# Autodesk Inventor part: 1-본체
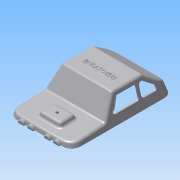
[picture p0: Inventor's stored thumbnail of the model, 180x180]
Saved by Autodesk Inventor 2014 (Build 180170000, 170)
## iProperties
Created: 2015-05
Part Number: 1-본체
Material: ABS 플라스틱
Document SubType Name: Modeling
Designer: Administrator
Density: 1.06 g/cm^3
Appearance: 매끄러움 - 흰색
Mass: 31.0436 g
Surface Area: 303.905 cm^2
Volume: 29.2864 cm^3
Author: Administrator
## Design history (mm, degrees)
sketch "스케치1"
  geometry: L1 (-61, 0)-(61, 0); L2 (61, 0)-(58.321, -10); L3 (-61, 0)-(-59.66, -5); L4 (-59.66, -5)-(-19, -7.131); L5 (-19, -7.131)-(-4.71, -30); L6 (-4.71, -30)-(31, -30); L7 (31, -30)-(58.321, -10); 2 further points
  constraints: 14 end point, 1 coincident, 1 horizontal, 1 midpoint, 1 parallel
  dimensions: "d28" = 122 distance of L1.start L1.end; "d29" = 105 deg angle of L1 L2; "d30" = 105 deg angle of L1 L3; "d31" = 3 deg angle of L1 L4; "d32" = 5 vertical distance of L1.start L3.end; "d33" = 125 deg angle of L5 L4; "d34" = 42 horizontal distance of L4.end L1.start; "d35" = 30 distance between parallel lines of L1 L6; "d36" = 30 horizontal distance of L1.end L6.end; "d37" = 20 vertical distance of L2.end L6.end
extrude "돌출1" new body sketch "스케치1" stored distance "d12" = 76; taper "d13" = 0 deg
node "작업 평면1"
sketch "스케치2"
  geometry: L1 (0, 38)-(0, -38) reference; L2 (-30, 38)-(-30, -38) reference; L3 (0, -38)-(-30, -29.962); L4 (0, 38)-(-30, 29.962); L5 (-30, -38)-(0, -38); L6 (-30, 38)-(0, 38); 3 further points
  constraints: 8 end point, 2 point on line, 1 parallel, 1 perpendicular
  dimensions: "d39" = 105 deg angle of L1 L3; "d40" = 105 deg angle of L1 L4
extrude "돌출2" cut sketch "스케치2" stored distance "d41" = 76; taper "d42" = 0 deg
sketch "스케치4"
  geometry: L1 (-59.66, -5)-(-19, -7.131) reference; L2 (-50.015, -5.505)-(-48.459, -10.594); L3 (-48.459, -10.594)-(-32.122, -11.45); L4 (-32.122, -11.45)-(-30.042, -6.552); 1 further point
  constraints: 6 end point, 2 point on line, 1 parallel
  dimensions: "d65" = 20 distance of L4.end L2.start
extrude "돌출4" join sketch "스케치4" stored distance "d68" = 26; taper "d69" = 0 deg
fillet "모깎기6" dims "d139" = 12
fillet "모깎기2" dims "d101" = 3
fillet "모깎기3" dims "d102" = 3
fillet "모깎기4" dims "d103" = 3
fillet "모깎기5" dims "d104" = 3
feature "쉘1" dims "d43" = 2
sketch "스케치3"
  geometry: L1 (-58.321, -10)-(-31, -30) reference; L2 (-31, -30)-(4.71, -30) reference; L3 (4.71, -30)-(19, -7.131) reference; L4 (2.819, -23.59)-(8.443, -14.59); L5 (5.899, -10)-(-19.689, -10); L6 (-22.689, -13)-(-22.689, -22); L7 (-19.689, -25)-(0.275, -25); L8 (-25.385, -22)-(-25.385, -13); L9 (-28.385, -10)-(-40.679, -10); L10 (-30.157, -24.421)-(-42.451, -15.421); A1 r 3 centre (5.899, -13) between (8.443, -14.59) and (5.899, -10); A2 r 3 centre (0.275, -22) between (0.275, -25) and (2.819, -23.59); A3 r 3 centre (-19.689, -13) between (-19.689, -10) and (-22.689, -13); A4 r 3 centre (-19.689, -22) between (-22.689, -22) and (-19.689, -25); A5 r 3 centre (-28.385, -22) between (-30.157, -24.421) and (-25.385, -22); A6 r 3 centre (-28.385, -13) between (-25.385, -13) and (-28.385, -10); A7 r 3 centre (-40.679, -13) between (-40.679, -10) and (-42.451, -15.421); 2 further points
  constraints: 14 end point, 14 point on circle, 14 tangent, 7 centre point, 4 perpendicular, 3 equal radius, 3 parallel, 2 point on line
  dimensions: "d45" = 5 distance between parallel lines of L3 L4; "d46" = 15 distance between parallel lines of L5 L7; "d47" = 34 distance from line of L6 point (11.311, -10); "d48" = 3 radius of A1; "d53" = 5 distance between parallel lines of L2 L7; "d54" = 3 radius of A5; "d55" = 5 distance edge to line of A5 L2; "d56" = 15 dimension on A5 L9; "d57" = 3 radius of A6; "d58" = 5 distance between parallel lines of L1 L10; "d59" = 3 radius of A7
extrude "돌출3" cut sketch "스케치3" stored distance "d60" = 76; taper "d61" = 0 deg
sketch "스케치6"
  geometry: L1 (-61, 38)-(-61, -38) reference; C1 r 3 at (-40, 0); C2 r 3 at (40, 0); C3 r 3 at (0, -22); C4 r 3 at (0, 22); 3 further points
  constraints: 4 centre point, 2 equal radius, 2 horizontal alignment, 1 vertical alignment
  dimensions: "d74" = 6 diameter of C2; "d75" = 6 diameter of C1; "d76" = 21 distance from line of C1.centre L1; "d77" = 40 horizontal distance of C3.centre C1.centre; "d78" = 40 horizontal distance of C2.centre C3.centre; "d79" = 44 distance of C4.centre C3.centre; "d80" = 22 distance of C3.centre point (0, 0)
extrude "돌출6" join sketch "스케치6" stored distance "d81" = 1; taper "d82" = 2 deg
node "작업 평면2"
sketch "스케치8"
  geometry: L1 (0, 26.409)-(0, 38) reference; L2 (0, -38)-(0, -26.409) reference; L3 (0, 25)-(0, 17); L4 (0, 14)-(0, 6); L5 (0, -6)-(0, -14); L6 (0, -17)-(0, -25); A1 r 4 centre (0, 10) between (0, 6) and (0, 14); A2 r 4 centre (0, 21) between (0, 17) and (0, 25); A3 r 4 centre (0, -10) between (0, -14) and (0, -6); A4 r 4 centre (0, -21) between (0, -25) and (0, -17); 1 further point
  constraints: 8 end point, 8 point on circle, 4 centre point, 3 equal radius, 13 other
  dimensions: "d106" = 10 distance of A1.centre point (0, 0); "d108" = 4 radius of A1; "d109" = 11 distance of A2.centre A1.centre; "d110" = 20 distance of A3.centre A1.centre; "d111" = 11 distance of A4.centre A3.centre
extrude "돌출8" join sketch "스케치8" distance "d112" = 3.5; taper "d113" = 0 deg
sketch "스케치11"
  geometry: L1 (-45, -2)-(-35, -2); L2 (-35, -2)-(-33.557, -10.181); L3 (-33.557, -10.181)-(-46.443, -10.181); L4 (-46.443, -10.181)-(-45, -2); L5 (35, -2)-(45, -2); L6 (45, -2)-(47.646, -17.004); L7 (35, -2)-(30.088, -29.857); L8 (30.157, -24.421)-(42.451, -15.421) reference; L9 (40.679, -10)-(28.385, -10) reference; L10 (25.385, -13)-(25.385, -22) reference; L11 (19.689, -10)-(-5.899, -10) reference; L12 (-8.443, -14.59)-(-2.819, -23.59) reference; L13 (-0.275, -25)-(19.689, -25) reference; L14 (22.689, -22)-(22.689, -13) reference; L15 (-49.409, 0)-(49.409, 0) reference; L16 (-37, 0)-(-36.678, -9.209) reference; L17 (-43, 0)-(-43.309, -8.861) reference; L18 (37, 0)-(36.171, -23.736) reference; L19 (43, 0)-(43.638, -18.27) reference; L20 (30.088, -29.857)-(47.646, -17.004); L21 (-48.509, -3.357)-(-20.403, -4.83) reference; L22 (-49.409, 0)-(-48.509, -3.357) reference; L23 (44.881, -16.897)-(49.409, 0) reference; L24 (30.019, -27.776)-(44.881, -16.897) reference; L25 (-3.047, -27.776)-(30.019, -27.776) reference; L26 (-15.628, -7.642)-(-3.047, -27.776) reference; A1 r 3 centre (28.385, -22) between (25.385, -22) and (30.157, -24.421) reference; A2 r 3 centre (40.679, -13) between (42.451, -15.421) and (40.679, -10) reference; A3 r 3 centre (28.385, -13) between (28.385, -10) and (25.385, -13) reference; A4 r 3 centre (19.689, -13) between (22.689, -13) and (19.689, -10) reference; A5 r 3 centre (-5.899, -13) between (-5.899, -10) and (-8.443, -14.59) reference; A6 r 3 centre (-0.275, -22) between (-2.819, -23.59) and (-0.275, -25) reference; A7 r 3 centre (19.689, -22) between (19.689, -25) and (22.689, -22) reference; A8 r 6 centre (-20.717, -10.822) between (-15.628, -7.642) and (-20.403, -4.83) reference; 7 further points
  constraints: 16 end point, 3 parallel, 2 coincident, 1 horizontal, 1 other
  dimensions: "d115" = 80 deg angle to the sketch x axis of L4; "d116" = 80 deg angle to the sketch x axis of L2; "d117" = 2 distance of the line from the sketch origin of L1; "d118" = 2 horizontal distance of point (-37, 0) L1.end; "d119" = 2 horizontal distance of point (-43, 0) L1.start; "d120" = 12.8852 distance of L2.end L3.end; "d121" = 2 horizontal distance of L18.start L5.start; "d122" = 2 horizontal distance of L19.start L5.end; "d123" = 80 deg angle to the sketch x axis of L7; "d124" = 2 distance of the line from the sketch origin of L5; "d125" = 21.75929 distance of L7.end L6.end
extrude "돌출9" join sketch "스케치11" stored distance "d126" = 2; taper "d127" = 0 deg
node "작업 평면4"
node "작업 평면5"
sketch "스케치12"
  geometry: L1 (-61.287, 7.01)-(-51.287, 7.01); L2 (-51.287, 7.01)-(-46.532, -19.954); L3 (-61.287, 7.01)-(-64.014, -8.455); L4 (-105.696, 9.01)-(-6.878, 9.01) reference; L5 (-59.287, 9.01)-(-60.245, -18.419) reference; L6 (-64.014, -8.455)-(-64.793, -12.874); L7 (-64.793, -12.874)-(-60.29, -19.474); L8 (-60.29, -19.474)-(-46.532, -19.954); 6 further points
  constraints: 12 end point, 1 coincident, 1 collinear, 1 horizontal, 1 perpendicular
  dimensions: "d129" = 80 deg angle of L4 L3; "d130" = 80 deg angle of L4 L2; "d131" = 10 distance of L1.start L1.end; "d132" = 2 distance between parallel lines of L4 L1; "d133" = 2 horizontal distance of L1.start point (-59.287, 9.01); "d134" = 13.75762 horizontal distance of L7.end L2.end; "d135" = 6.59969 vertical distance of L6.end L7.end; "d136" = 18.26068 horizontal distance of L2.end L6.end
extrude "돌출10" join sketch "스케치12" stored distance "d137" = 2; taper "d138" = 0 deg
sketch "스케치13"
  geometry: L1 (64.047, 54.068)-(64.047, 1.251) reference; 2 further points
  constraints: 1 horizontal alignment, 1 other
  dimensions: "d140" = 50 distance from line of L1 point (14.047, 27.66)
feature "엠보싱1" sketch "스케치13" dims "d141" = 0.5, "d142" = 0
sketch "스케치14"
  geometry: C1 r 3 at (0, 0) reference; C2 r 3 at (-40, -22) reference; C3 r 3 at (0, -44) reference; C4 r 3 at (40, -22) reference; 4 further points
  constraints: 3 coincident
hole "구멍1" sketch "스케치14" at (0, -44), (40, -22), (0, 0) diameter "d143" = 3.242; stored, may be unused: countersink angle "d147" = 90 deg, drill point angle "d149" = 118 deg; dims "d144" = 9, "d145" = 4, "d146" = 2, "d148" = 11
sketch "스케치15"
  geometry: L1 (0.139, 73.929)-(98.679, 73.929) reference; L2 (108.338, 64.27)-(108.338, 11.73) reference; L3 (98.679, 2.071)-(0.139, 2.071) reference; L4 (-9.521, 11.73)-(-9.521, 64.27) reference; L5 (98.679, 74.929)-(0.139, 74.929); L6 (-10.521, 64.27)-(-10.521, 11.73); L7 (0.139, 1.071)-(98.679, 1.071); L8 (109.338, 11.73)-(109.338, 64.27); 5 further points; 4 other entities
  constraints: 8 end point, 7 parallel, 16 other
  dimensions: "d150" = 1 distance between parallel lines of L1 L5
extrude "돌출11" join sketch "스케치15" distance "d151" = 1; taper "d152" = 0 deg
hole "구멍2" diameter "d155" = 3.242; stored, may be unused: countersink angle "d159" = 90 deg, drill point angle "d161" = 118 deg; dims "d153" = 10, "d154" = 10, "d156" = 9, "d157" = 4, "d158" = 2, "d160" = 11
chamfer "모따기1" distance "d162" = 1; stored, may be unused: second distance "d163" = 2, angle "d164" = 45 deg
node "솔리드1"
mirror "대칭1"
node "투영된 루프7"
node "투영된 루프8"
node "투영된 루프9"
node "투영된 루프10"
other parameters: "d38" = 61, "d105" = -63, "d128" = -22
